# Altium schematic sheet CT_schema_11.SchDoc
size 274 x 160 mm
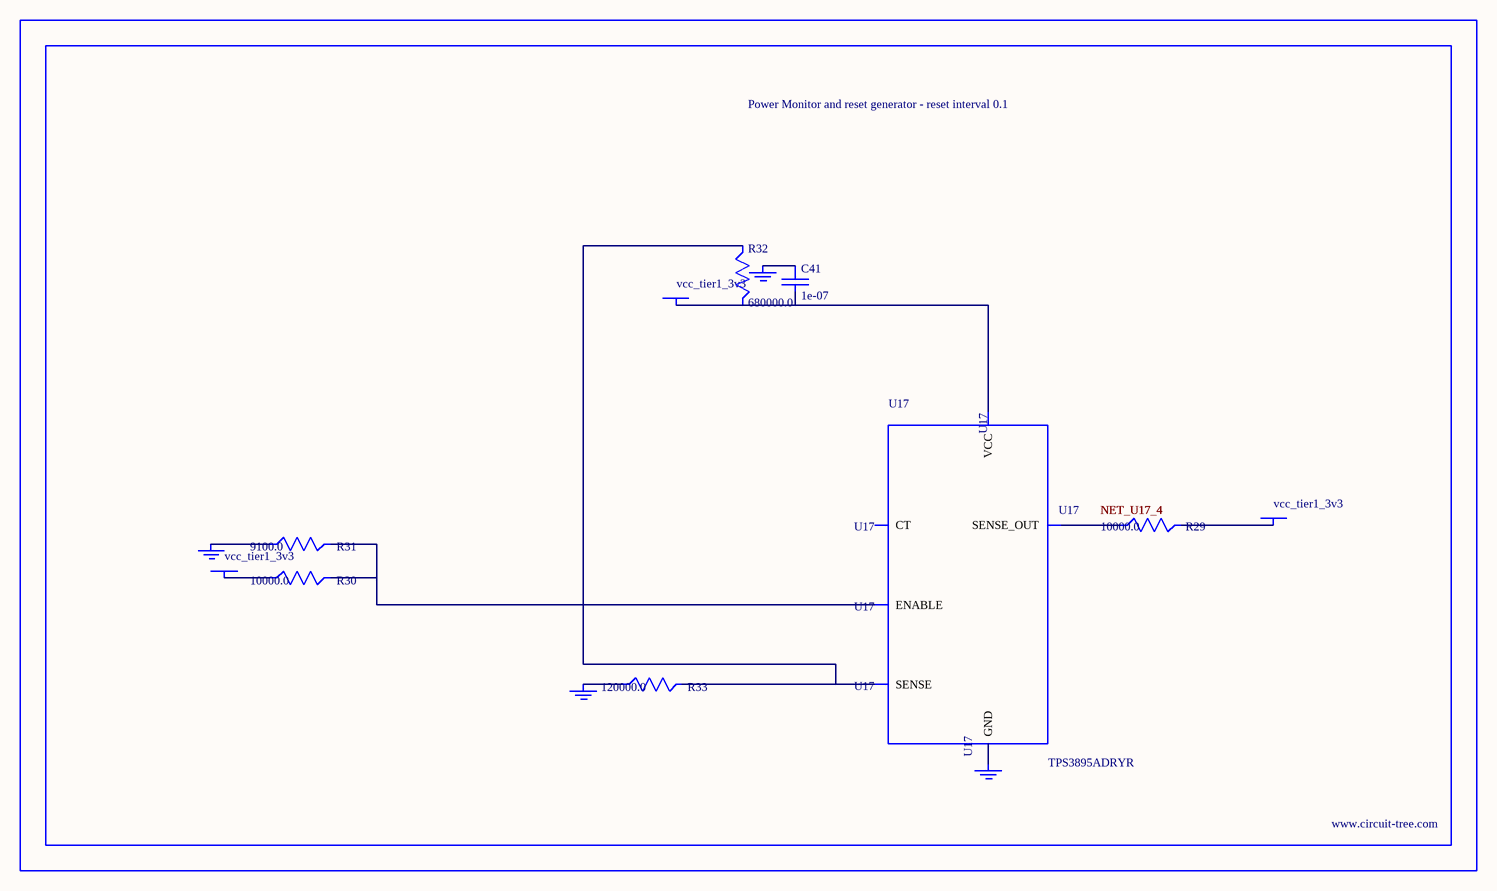
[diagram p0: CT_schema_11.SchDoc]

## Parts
BORDER10  (no value)
C41  1e-07  [C0402]
GND_INSTANCE_10_0  (no value)
GND_INSTANCE_10_1  (no value)
GND_INSTANCE_10_2  (no value)
GND_INSTANCE_10_3  (no value)
POWER_INSTANCE_10_0  vcc_tier1_3v3
POWER_INSTANCE_10_1  vcc_tier1_3v3
POWER_INSTANCE_10_2  vcc_tier1_3v3
R29  10000.0  [R0603]
R30  10000.0  [R0603]
R31  9100.0  [R0603]
R32  680000.0  [R0603]
R33  120000.0  [R0603]
U17  TPS3895ADRYR  [SON-6]

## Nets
NetC41_1: C41.1 GND_INSTANCE_10_2.0(GND)
NetC41_2: C41.2 POWER_INSTANCE_10_2.0(PWR) R32.2 U17.6(VCC)
NetGND_INSTANCE_10_0_0: GND_INSTANCE_10_0.0(GND) R31.1
NetGND_INSTANCE_10_1_0: GND_INSTANCE_10_1.0(GND) R33.1
NetGND_INSTANCE_10_3_0: GND_INSTANCE_10_3.0(GND) U17.2(GND)
NetPOWER_INSTANCE_10_0_0: POWER_INSTANCE_10_0.0(PWR) R30.1
NetPOWER_INSTANCE_10_1_0: POWER_INSTANCE_10_1.0(PWR) R29.2
NetR29_1: R29.1 U17.4(SENSE_OUT)
NetR30_2: R30.2 R31.2 U17.1(ENABLE)
NetR32_1: R32.1 R33.2 U17.3(SENSE)

Not connected (* = marked no-connect by the designer): U17 5(CT)

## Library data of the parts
BORDER10 = BORDER_PAGE10
C41 = C0402C104K3RACTU
GND_INSTANCE_10_0-GND_INSTANCE_10_3 = GND
POWER_INSTANCE_10_0-POWER_INSTANCE_10_2 = PWR
R29 R30 = RC0603JR-0710KL
R31 = RC0603JR-079K1L
R32 = RC0603JR-07680KL
R33 = RC0603JR-07120KL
